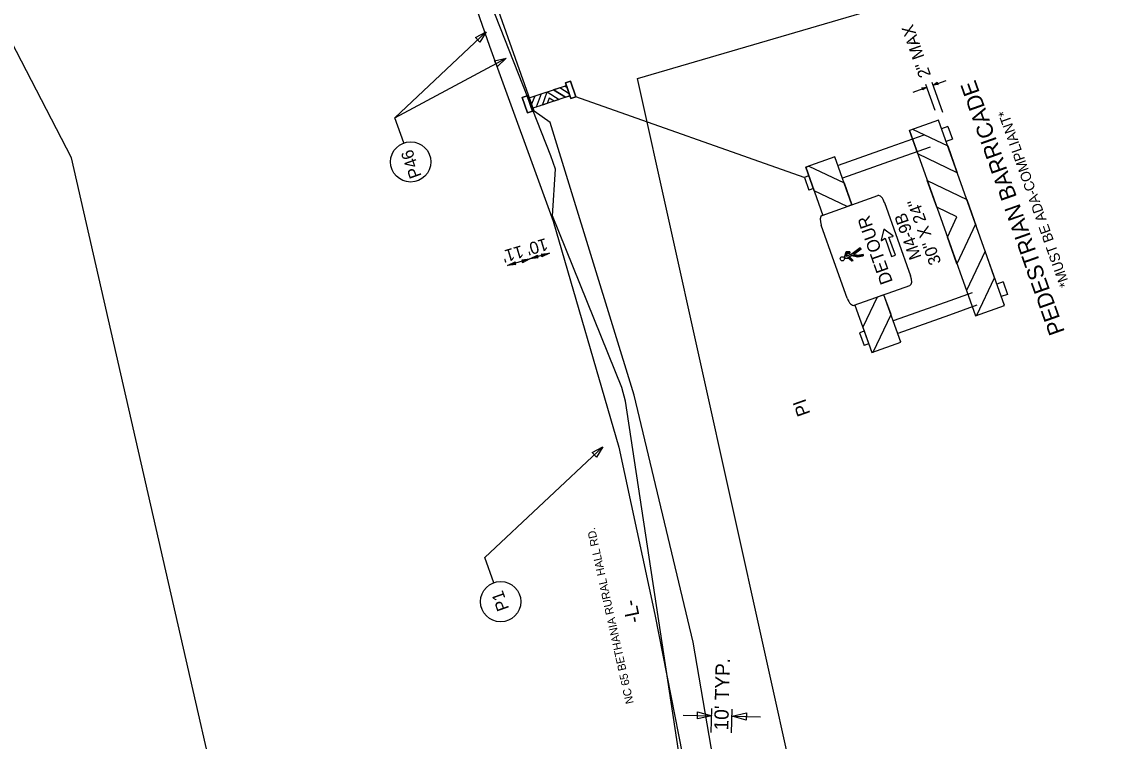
# Model space of a CAD drawing. Extents: x 1615843 to 1618439, y 899470 to 903922.
# Drawn here: x 1616337 to 1616867, y 902639 to 902993 of the extents above; entities that cross this region are included whole.
import ezdxf

# ---------------------------------------------------------------- set-up
doc = ezdxf.new("R2010")
doc.units = 0
for name, color, linetype in [('Default', 7, 'Continuous'), ('DEV PED BARRICADE SECTION VIEW CELL', 7, 'Continuous'), ('DEV PED BARRICDE PLAN VIEW CELL', 7, 'Continuous'), ('GS M4-9b CELL', 7, 'Continuous'), ('Old_Level_11', 7, 'Continuous'), ('Prop Horizontal Alignment Tick Label', 7, 'Continuous'), ('Scratch_Level_5', 7, 'Continuous'), ('Sheet Clip Boundary CELL', 7, 'Continuous'), ('Text', 7, 'Continuous')]:
    doc.layers.add(name, color=color, linetype=linetype)

msp = doc.modelspace()

# ---------------------------------------------------------------- linework, layer by layer
at = {"layer": 'Default'}
for p, q in [((1616520.52, 902945.76), (1616575.23, 902975.04)), ((1616721.55, 902916.3), (1616609.32, 902956.05))]:
    msp.add_line(p, q, dxfattribs=at)
for points in [[(1616524.93, 902933.35), (1616520.52, 902945.76), (1616565.4, 902987.94)], [(1616569.15, 902717.21), (1616564.73, 902729.62), (1616622.65, 902784.05)]]:
    msp.add_lwpolyline(points, dxfattribs=at)
for points in [[(1616560.11, 902985.11), (1616565.4, 902987.94), (1616562.24, 902982.84)], [(1616569.39, 902973.67), (1616575.23, 902975.04), (1616570.86, 902970.93)], [(1616582.77, 902875.83), (1616586.85, 902876.32), (1616583.15, 902874.47), (1616583.44, 902875.3)], [(1616590.93, 902876.8), (1616586.85, 902876.32), (1616590.55, 902878.17), (1616590.26, 902877.33)], [(1616592.35, 902878.68), (1616596.44, 902879.16), (1616592.74, 902877.31), (1616593.03, 902878.15)], [(1616579.95, 902873.54), (1616575.87, 902873.06), (1616579.57, 902874.91), (1616579.28, 902874.07)], [(1616617.36, 902781.21), (1616622.65, 902784.05), (1616619.49, 902778.95)]]:
    msp.add_lwpolyline(points, close=True, dxfattribs=at)
for centre in [(1616528.24, 902924.03), (1616572.46, 902707.88)]:
    msp.add_circle(centre, 9.89, dxfattribs=at)
at = {"layer": 'DEV PED BARRICADE SECTION VIEW CELL'}
for p, q in [((1616775.1, 902958.35), (1616781.73, 902960.71)), ((1616779.33, 902960.47), (1616781.73, 902960.71)), ((1616779.33, 902960.47), (1616781.73, 902960.71)), ((1616780.08, 902960.12), (1616779.33, 902960.47)), ((1616780.08, 902960.12), (1616779.33, 902960.47)), ((1616781.73, 902960.71), (1616779.72, 902959.37)), ((1616781.73, 902960.71), (1616779.72, 902959.37)), ((1616785.78, 902949.33), (1616781.27, 902962.02)), ((1616789.63, 902948.3), (1616784.36, 902963.12)), ((1616784.83, 902961.81), (1616786.84, 902963.14)), ((1616784.83, 902961.81), (1616786.84, 902963.14)), ((1616787.23, 902962.04), (1616784.83, 902961.81)), ((1616787.23, 902962.04), (1616784.83, 902961.81)), ((1616785.28, 902961.97), (1616791.28, 902964.1)), ((1616786.84, 902963.14), (1616786.48, 902962.4)), ((1616786.84, 902963.14), (1616786.48, 902962.4)), ((1616786.48, 902962.4), (1616787.23, 902962.04)), ((1616786.48, 902962.4), (1616787.23, 902962.04)), ((1616779.72, 902959.37), (1616780.08, 902960.12)), ((1616779.72, 902959.37), (1616780.08, 902960.12)), ((1616787.45, 902944.61), (1616773.16, 902939.53)), ((1616819.85, 902853.48), (1616787.45, 902944.61)), ((1616773.16, 902939.53), (1616805.56, 902848.4)), ((1616777.28, 902927.94), (1616773.16, 902939.53)), ((1616792.09, 902941.38), (1616788.99, 902940.28)), ((1616792.09, 902941.38), (1616794.29, 902935.19)), ((1616780.25, 902937.17), (1616763.56, 902931.24)), ((1616794.29, 902935.19), (1616791.19, 902934.09)), ((1616763.56, 902931.24), (1616738.12, 902922.19)), ((1616783.33, 902931.3), (1616765.76, 902925.05)), ((1616791.99, 902931.85), (1616796.66, 902918.73)), ((1616736.58, 902926.53), (1616722.29, 902921.44)), ((1616744.97, 902902.93), (1616736.58, 902926.53)), ((1616765.76, 902925.05), (1616740.32, 902916.01)), ((1616796.66, 902918.73), (1616777.28, 902927.94)), ((1616722.29, 902921.44), (1616730.72, 902897.74)), ((1616726.41, 902909.86), (1616722.29, 902921.44)), ((1616723.83, 902917.11), (1616721.55, 902916.3)), ((1616721.6, 902916.32), (1616723.8, 902910.13)), ((1616786.61, 902901.7), (1616781.94, 902914.82)), ((1616781.94, 902914.82), (1616801.32, 902905.61)), ((1616726.03, 902910.92), (1616723.8, 902910.13)), ((1616742.69, 902902.12), (1616726.41, 902909.86)), ((1616801.32, 902905.61), (1616805.98, 902892.49)), ((1616796.51, 902897), (1616786.61, 902901.7)), ((1616791.8, 902887.1), (1616796.51, 902897)), ((1616805.68, 902893.35), (1616796.46, 902873.98)), ((1616796.46, 902873.98), (1616791.8, 902887.1)), ((1616810.34, 902880.23), (1616801.13, 902860.86)), ((1616815.01, 902867.12), (1616810.34, 902880.23)), ((1616819.21, 902865.11), (1616816.11, 902864.01)), ((1616819.21, 902865.11), (1616821.41, 902858.92)), ((1616804.03, 902859.71), (1616790.68, 902854.96)), ((1616801.13, 902860.86), (1616805.56, 902848.4)), ((1616757.29, 902857.56), (1616750.26, 902842.77)), ((1616768.98, 902835.4), (1616760.68, 902858.76)), ((1616790.68, 902854.96), (1616765.24, 902845.92)), ((1616821.41, 902858.92), (1616818.31, 902857.82)), ((1616746.38, 902853.68), (1616754.69, 902830.32)), ((1616806.32, 902853.55), (1616792.88, 902848.77)), ((1616805.56, 902848.4), (1616819.85, 902853.48)), ((1616819.67, 902854), (1616819.34, 902853.3)), ((1616819.85, 902853.48), (1616819.67, 902854)), ((1616792.88, 902848.77), (1616767.44, 902839.73)), ((1616750.95, 902840.84), (1616748.72, 902840.05)), ((1616748.72, 902840.05), (1616750.92, 902833.86)), ((1616750.26, 902842.77), (1616754.69, 902830.32)), ((1616753.15, 902834.65), (1616750.92, 902833.86)), ((1616754.69, 902830.32), (1616768.98, 902835.4)), ((1616768.8, 902835.91), (1616768.47, 902835.22)), ((1616768.98, 902835.4), (1616768.8, 902835.91))]:
    msp.add_line(p, q, dxfattribs=at)
for points in [[(1616773.16, 902939.53), (1616774.69, 902940.07), (1616791.99, 902931.85)], [(1616722.29, 902921.44), (1616723.82, 902921.99), (1616741.12, 902913.76)], [(1616741.12, 902913.76), (1616744.97, 902902.93), (1616742.69, 902902.12)], [(1616805.56, 902848.4), (1616806.22, 902848.64), (1616815.01, 902867.12)], [(1616764.14, 902849.03), (1616760.68, 902858.76), (1616757.29, 902857.56)], [(1616754.69, 902830.32), (1616755.35, 902830.55), (1616764.14, 902849.03)]]:
    msp.add_lwpolyline(points, dxfattribs=at)
at = {"layer": 'DEV PED BARRICDE PLAN VIEW CELL'}
for p, q in [((1616585.96, 902955.28), (1616604.74, 902961.54)), ((1616601.46, 902960.45), (1616598.46, 902959.45)), ((1616606.1, 902957.44), (1616601.46, 902960.45)), ((1616604.74, 902961.54), (1616604.1, 902961.33)), ((1616604.1, 902961.33), (1616605.04, 902960.64)), ((1616604.31, 902962.81), (1616606.79, 902963.64)), ((1616606.84, 902955.22), (1616604.31, 902962.81)), ((1616605.04, 902960.64), (1616604.74, 902961.54)), ((1616604.74, 902961.54), (1616606.42, 902956.5)), ((1616605.04, 902960.64), (1616605.04, 902960.64)), ((1616606.79, 902963.64), (1616609.32, 902956.05)), ((1616583.06, 902955.72), (1616585.54, 902956.55)), ((1616585.59, 902948.13), (1616583.06, 902955.72)), ((1616585.54, 902956.55), (1616588.07, 902948.96)), ((1616585.96, 902955.28), (1616586.6, 902955.49)), ((1616586.18, 902954.61), (1616585.96, 902955.28)), ((1616587.64, 902950.23), (1616585.96, 902955.28)), ((1616586.6, 902955.49), (1616586.18, 902954.61)), ((1616586.6, 902955.49), (1616586.6, 902955.49)), ((1616592.4, 902957.42), (1616589.85, 902950.95)), ((1616606.42, 902956.5), (1616592.24, 902951.77)), ((1616592.95, 902951.99), (1616595.33, 902958.4)), ((1616595.33, 902958.4), (1616601.26, 902954.76)), ((1616604.29, 902955.79), (1616598.46, 902959.45)), ((1616598.46, 902959.45), (1616604.29, 902955.79)), ((1616604.29, 902955.79), (1616606.42, 902956.5)), ((1616609.32, 902956.05), (1616606.84, 902955.22)), ((1616591.83, 902951.63), (1616587.64, 902950.23)), ((1616589.85, 902950.95), (1616587.64, 902950.23)), ((1616592.24, 902951.77), (1616591.83, 902951.63)), ((1616588.07, 902948.96), (1616585.59, 902948.13))]:
    msp.add_line(p, q, dxfattribs=at)
for points in [[(1616606.42, 902956.5), (1616606.1, 902957.44), (1616601.46, 902960.45)], [(1616587.64, 902950.23), (1616587.27, 902951.34), (1616589.44, 902956.44)], [(1616589.44, 902956.44), (1616591.4, 902957.09), (1616592.4, 902957.42)], [(1616601.26, 902954.76), (1616598.75, 902953.94), (1616596.33, 902955.42), (1616595.31, 902952.77), (1616592.95, 902951.99)]]:
    msp.add_lwpolyline(points, dxfattribs=at)
for points in [[(1616609.32, 902956.05), (1616606.79, 902963.64), (1616604.31, 902962.81), (1616606.84, 902955.22)], [(1616588.07, 902948.96), (1616585.54, 902956.55), (1616583.06, 902955.72), (1616585.59, 902948.13)]]:
    msp.add_lwpolyline(points, close=True, dxfattribs=at)
at = {"layer": 'GS M4-9b CELL'}
for p, q in [((1616761.01, 902903.99), (1616767.4, 902886.03)), ((1616760.65, 902891.04), (1616759.24, 902885.6)), ((1616759.5, 902885.39), (1616761.23, 902886.5)), ((1616765.1, 902887.65), (1616760.65, 902891.04)), ((1616761.23, 902886.5), (1616764.41, 902877.55)), ((1616763.11, 902887.1), (1616765.02, 902887.31)), ((1616766.27, 902878.21), (1616763.11, 902887.1)), ((1616745.14, 902878.91), (1616749.07, 902881.82)), ((1616749.07, 902881.82), (1616745.14, 902878.91)), ((1616749.44, 902881.32), (1616745.64, 902878.5)), ((1616745.64, 902878.5), (1616749.44, 902881.32)), ((1616749.07, 902881.82), (1616749.44, 902881.32)), ((1616749.44, 902881.32), (1616749.07, 902881.82)), ((1616767.4, 902886.03), (1616773.78, 902868.07)), ((1616741.79, 902876.63), (1616741.3, 902877.28)), ((1616741.3, 902877.28), (1616741.79, 902876.63)), ((1616741.79, 902876.63), (1616743.58, 902876.5)), ((1616744.94, 902877.99), (1616742.9, 902877.08)), ((1616742.9, 902877.08), (1616744.94, 902877.99)), ((1616744.01, 902877.01), (1616742.9, 902877.08)), ((1616743.58, 902876.5), (1616744.89, 902875.37)), ((1616745.62, 902875.62), (1616744.01, 902877.01)), ((1616745.62, 902875.62), (1616744.89, 902875.37)), ((1616744.89, 902875.37), (1616745.62, 902875.62)), ((1616747.74, 902877.4), (1616744.94, 902877.99)), ((1616744.94, 902877.99), (1616747.74, 902877.4)), ((1616745.64, 902878.5), (1616747.77, 902878.05)), ((1616747.77, 902878.05), (1616745.64, 902878.5)), ((1616750.52, 902877.83), (1616747.74, 902877.4)), ((1616747.74, 902877.4), (1616750.52, 902877.83)), ((1616747.77, 902878.05), (1616750.42, 902878.47)), ((1616750.42, 902878.47), (1616747.77, 902878.05)), ((1616750.42, 902878.47), (1616750.52, 902877.83)), ((1616750.52, 902877.83), (1616750.42, 902878.47)), ((1616764.41, 902877.55), (1616766.27, 902878.21))]:
    msp.add_line(p, q, dxfattribs=at)
for points in [[(1616730.27, 902897.7), (1616757.73, 902907.46)], [(1616736.3, 902874.97), (1616729.92, 902892.93)], [(1616741.3, 902877.28), (1616742.08, 902879.78), (1616743.91, 902879.85), (1616743.93, 902879.23), (1616742.54, 902879.18), (1616742.1, 902877.77), (1616745.14, 902878.91)], [(1616745.14, 902878.91), (1616742.1, 902877.77), (1616742.54, 902879.18), (1616743.93, 902879.23), (1616743.91, 902879.85), (1616742.08, 902879.78), (1616741.3, 902877.28)], [(1616744.89, 902875.37), (1616743.58, 902876.5), (1616741.79, 902876.63)], [(1616742.9, 902877.08), (1616744.01, 902877.01), (1616745.62, 902875.62)], [(1616742.69, 902857.01), (1616736.3, 902874.97)], [(1616742.69, 902857.01), (1616736.3, 902874.97)], [(1616745.97, 902853.53), (1616773.43, 902863.3)]]:
    msp.add_lwpolyline(points, dxfattribs=at)
msp.add_circle((1616740.23, 902876.42), 1.02, dxfattribs=at)
for centre, start, end in [((1616764.99, 902887.5), 277.001, 55.6629), ((1616759.4, 902885.56), 163.4785, 302.1404)]:
    msp.add_arc(centre, 0.182, start, end, dxfattribs=at)
for centre, major_axis, start_param, end_param in [((1616759.2, 902903.34), (1.47, -4.12), 1.570796, 3.141593), ((1616731.73, 902893.58), (-1.47, 4.12), 0, 1.570796), ((1616771.97, 902867.42), (1.47, -4.12), 0, 1.570796), ((1616744.5, 902857.66), (1.47, -4.12), 4.712162, 6.283185)]:
    msp.add_ellipse(centre, major_axis=major_axis, ratio=0.44, start_param=start_param, end_param=end_param, dxfattribs=at)
at = {"layer": 'Old_Level_11'}
msp.add_line((1616596.44, 902879.16), (1616575.87, 902873.06), dxfattribs=at)
at = {"layer": 'Scratch_Level_5'}
for points in [[(1616705.54, 902373.67), (1616699.85, 902458.96), (1616686.62, 902573.2), (1616667.04, 902687.93), (1616638.01, 902809.43), (1616596.83, 902943.32), (1616588.98, 902949.04), (1616499.35, 903201.92), (1616504.06, 903203.6), (1616506.92, 903204.49), (1616400, 903496.37), (1616388.07, 903529.07), (1616755.41, 903693.55), (1617118.27, 903131.4), (1617302.81, 902506.85), (1616959.09, 902384.66)], [(1616699.32, 902373.4), (1616633.77, 902806.46), (1616631.94, 902813.22), (1616597.93, 902897.46), (1616599.33, 902920.4), (1616597.1, 902927.03), (1616370.6, 903502.2), (1616643.52, 903550.34), (1617118.27, 903131.4), (1617302.81, 902506.85), (1616959.09, 902384.66)]]:
    msp.add_lwpolyline(points, close=True, dxfattribs=at)
at = {"layer": 'Sheet Clip Boundary CELL'}
for points in [[(1616920.55, 902382.99), (1616489.91, 902364.33), (1616361.78, 902925.96), (1616113.49, 903406.12), (1616903.33, 903759.78), (1617118.27, 903131.4), (1617236.29, 902693.96), (1617083.45, 902390.05)], [(1616694.55, 902373.19), (1616732.15, 902374.79), (1616717.45, 902614.43), (1616639.68, 902965.04), (1616763.33, 903001.21), (1616761.22, 903018.27), (1616752.73, 903054.64), (1616632.71, 903026.28), (1616564.32, 903130.19), (1616414.61, 903540.98), (1616374.17, 903522.92), (1616456.37, 903298.56), (1616566.89, 902980.98), (1616598.23, 902894.85), (1616630.48, 902783.84), (1616648.21, 902701.52), (1616669.68, 902592.43), (1616683.11, 902510.03), (1616690.19, 902449.56), (1616690.27, 902434.92)]]:
    msp.add_lwpolyline(points, close=True, dxfattribs=at)
at = {"layer": 'Text'}
for p, q in [((1616675.88, 902643.62), (1616676.15, 902655.33)), ((1616685.88, 902643.39), (1616686.14, 902655.1)), ((1616662.07, 902652.14), (1616676.07, 902651.83)), ((1616686.06, 902651.6), (1616700.06, 902651.28))]:
    msp.add_line(p, q, dxfattribs=at)
for points in [[(1616669.11, 902653.74), (1616676.07, 902651.83), (1616669.03, 902650.24)], [(1616693.02, 902649.69), (1616686.06, 902651.6), (1616693.1, 902653.19)]]:
    msp.add_lwpolyline(points, close=True, dxfattribs=at)

# ---------------------------------------------------------------- texts
at = {"layer": 'Default'}
for s, height, rotation, p in [('P46', 6, 109.5707, (1616533.71, 902917.16)), ("10'", 6, 196.5191, (1616594.5, 902886.64)), ("11'", 6, 196.5191, (1616582.57, 902883.1)), ('NC 65 BETHANIA RURAL HALL RD.', 4, 102.4863, (1616637.83, 902658.08)), ('P1', 6, 109.5707, (1616576.69, 902704.5))]:
    msp.add_text(s, height=height, rotation=rotation, dxfattribs=at).set_placement(p)
at = {"layer": 'DEV PED BARRICADE SECTION VIEW CELL'}
for s, height, p in [('2" MAX', 6, (1616783.84, 902966.68)), ('PEDESTRIAN BARRICADE', 7.8816, (1616849.61, 902840.56)), ('*MUST BE ADA-COMPLIANT*', 5, (1616852.01, 902863.42))]:
    msp.add_text(s, height=height, rotation=109.5707, dxfattribs=at).set_placement(p)
at = {"layer": 'GS M4-9b CELL'}
for s, height, p in [("30'' X 24''", 6, (1616788.89, 902874.61)), ('DETOUR', 6.217, (1616765.11, 902865.13)), ('M4-9B', 6, (1616779.15, 902877.24))]:
    msp.add_text(s, height=height, rotation=109.5707, dxfattribs=at).set_placement(p)
at = {"layer": 'Prop Horizontal Alignment Tick Label'}
msp.add_text('-L-', height=7, rotation=101.7708, dxfattribs=at).set_placement((1616641.24, 902698.11))
at = {"layer": 'Sheet Clip Boundary CELL'}
msp.add_text('PI', height=6.5, rotation=109.5707, dxfattribs=at).set_placement((1616724.61, 902800.35))
at = {"layer": 'Text'}
msp.add_text("10' TYP.", height=7, rotation=88.6995, dxfattribs=at).set_placement((1616684.24, 902644.52))

doc.saveas('drawing.dxf')
